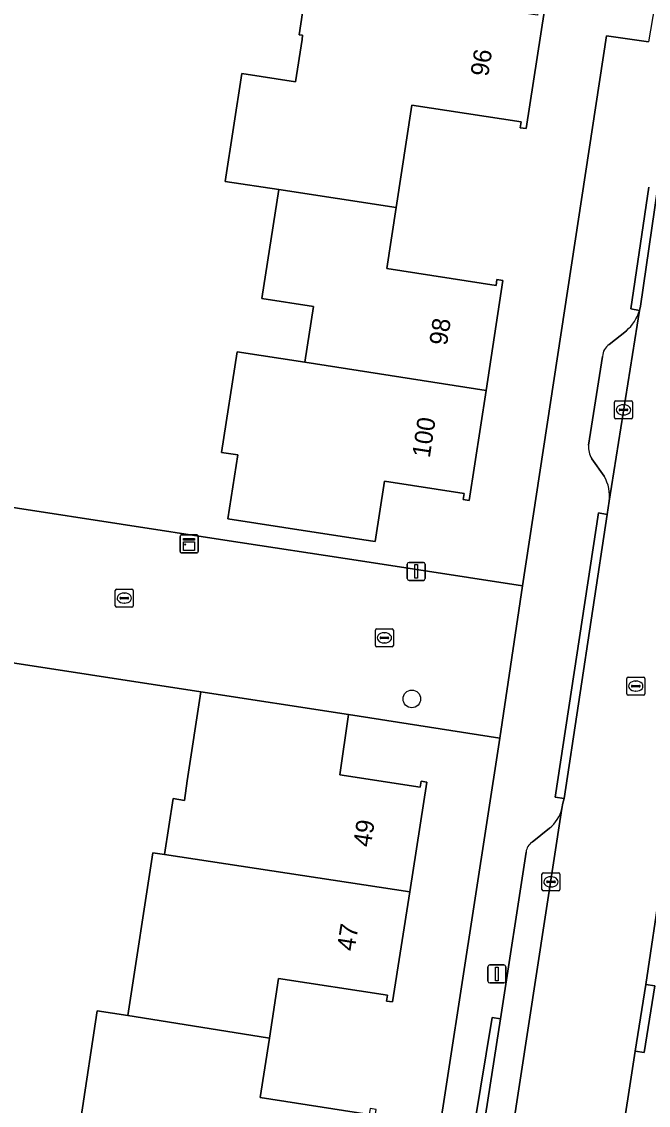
# Model space of a CAD drawing. Extents: x 161483 to 162250, y 379484 to 380833.
# Drawn here: x 161910.8 to 161945.6, y 380682.4 to 380742.6 of the extents above; entities that cross this region are included whole.
import ezdxf

# ---------------------------------------------------------------- set-up
doc = ezdxf.new("R2010")
doc.units = 0
for name, color, linetype in [('IMGEO_Boom', 7, 'Continuous'), ('IMGEO_Erf', 7, 'Continuous'), ('IMGEO_Kast', 7, 'Continuous'), ('IMGEO_Kolk', 7, 'Continuous'), ('IMGEO_Lichtmast', 7, 'Continuous'), ('IMGEO_Pand', 7, 'Continuous'), ('IMGEO_Pand_nummerreeks', 7, 'Continuous'), ('IMGEO_Parkeervlak_open', 7, 'Continuous'), ('IMGEO_Rijbaan_lokaal_open', 7, 'Continuous'), ('IMGEO_Rioolput', 7, 'Continuous'), ('IMGEO_Voetpad_open', 7, 'Continuous')]:
    doc.layers.add(name, color=color, linetype=linetype)

msp = doc.modelspace()

# ---------------------------------------------------------------- linework, layer by layer
at = {"layer": 'IMGEO_Boom'}
msp.add_circle((161932.436, 380704.97), 0.489, dxfattribs=at)
at = {"layer": 'IMGEO_Erf'}
for points in [[(161809.687, 380750), (161806.838, 380731.553), (161922.038, 380713.794), (161929.59, 380712.634), (161938.583, 380711.252), (161943.256, 380741.795), (161945.58, 380741.467)], [(161939.8, 380743.225), (161938.78, 380736.645), (161938.454, 380736.695), (161938.504, 380737.02), (161932.437, 380737.949), (161931.563, 380732.267), (161931.041, 380728.874), (161937.114, 380727.94), (161937.164, 380728.265), (161937.49, 380728.215), (161936.556, 380722.109), (161935.62, 380715.995), (161935.294, 380716.045), (161935.344, 380716.371), (161930.92, 380717.058), (161930.4, 380713.71), (161929.771, 380713.807), (161925.323, 380714.497), (161922.219, 380714.973), (161922.765, 380718.522), (161921.867, 380718.661), (161922.732, 380724.249), (161926.486, 380723.668), (161926.964, 380726.768), (161924.104, 380727.209), (161925.038, 380733.264), (161922.06, 380733.719), (161922.983, 380739.709), (161925.971, 380739.249), (161926.334, 380741.606), (161926.369, 380741.832), (161926.166, 380741.862), (161926.734, 380745.548)], [(161914.036, 380681.642), (161914.958, 380687.646), (161916.662, 380687.385), (161918.051, 380696.418), (161918.693, 380696.319), (161919.171, 380699.432), (161919.795, 380699.336), (161919.961, 380700.418), (161920.72, 380705.36), (161884.401, 380710.951), (161884.124, 380709.027), (161858.224, 380713.01), (161858.506, 380714.977), (161825.187, 380720.083)], [(161927.438, 380638.646), (161937.319, 380702.795), (161928.91, 380704.1), (161928.44, 380700.76), (161932.894, 380700.07), (161932.944, 380700.395), (161933.27, 380700.345), (161932.316, 380694.245), (161931.36, 380688.135), (161931.034, 380688.185), (161931.084, 380688.51), (161925.03, 380689.444), (161924.518, 380686.134), (161924.006, 380682.826), (161930.071, 380681.887)]]:
    msp.add_lwpolyline(points, dxfattribs=at)
at = {"layer": 'IMGEO_Kast'}
for p, q in [((161919.561, 380713.157), (161919.561, 380713.998)), ((161919.561, 380713.998), (161919.561, 380713.157)), ((161919.636, 380714.082), (161920.477, 380714.082)), ((161920.477, 380714.082), (161919.636, 380714.082)), ((161920.561, 380714.007), (161920.561, 380713.166)), ((161920.561, 380713.166), (161920.561, 380714.007)), ((161920.486, 380713.082), (161919.645, 380713.082)), ((161919.645, 380713.082), (161920.486, 380713.082))]:
    msp.add_line(p, q, dxfattribs=at)
for points in [[(161919.756, 380713.872), (161920.356, 380713.872), (161920.356, 380713.787), (161919.756, 380713.787), (161919.756, 380713.872)], [(161919.756, 380713.697), (161920.356, 380713.697), (161920.356, 380713.208), (161919.756, 380713.208), (161919.756, 380713.697)]]:
    msp.add_lwpolyline(points, dxfattribs=at)
msp.add_circle((161919.84, 380713.546), 0.0377, dxfattribs=at)
for centre, start, end in [((161919.639, 380714.004), 92.4484, 184.28452), ((161919.639, 380714.004), 92.4484, 184.28452), ((161920.483, 380714.004), 2.4484, 94.28452), ((161920.483, 380714.004), 2.4484, 94.28452), ((161919.639, 380713.16), 182.4484, 274.28452), ((161919.639, 380713.16), 182.4484, 274.28452), ((161920.483, 380713.16), 272.4484, 4.28452), ((161920.483, 380713.16), 272.4484, 4.28452)]:
    msp.add_arc(centre, 0.0779, start, end, dxfattribs=at)
at = {"layer": 'IMGEO_Kolk'}
for p, q in [((161943.691, 380720.601), (161943.691, 380721.453)), ((161943.766, 380721.527), (161944.618, 380721.527)), ((161944.179, 380721.307), (161944.204, 380721.307)), ((161944.692, 380721.453), (161944.692, 380720.601)), ((161943.95, 380721.021), (161943.95, 380721.033)), ((161944.388, 380720.984), (161943.99, 380720.984)), ((161943.993, 380721.07), (161944.391, 380721.07)), ((161944.202, 380720.747), (161944.177, 380720.747)), ((161944.434, 380721.033), (161944.434, 380721.021)), ((161944.618, 380720.527), (161943.766, 380720.527)), ((161915.959, 380710.142), (161915.959, 380710.994)), ((161916.034, 380711.068), (161916.886, 380711.068)), ((161916.96, 380710.994), (161916.96, 380710.142)), ((161916.218, 380710.562), (161916.218, 380710.574)), ((161916.656, 380710.525), (161916.258, 380710.525)), ((161916.261, 380710.611), (161916.659, 380710.611)), ((161916.447, 380710.848), (161916.472, 380710.848)), ((161916.702, 380710.574), (161916.702, 380710.562)), ((161916.886, 380710.068), (161916.034, 380710.068)), ((161916.47, 380710.288), (161916.445, 380710.288)), ((161930.407, 380707.936), (161930.407, 380708.788)), ((161930.482, 380708.862), (161931.334, 380708.862)), ((161930.895, 380708.642), (161930.92, 380708.642)), ((161931.408, 380708.788), (161931.408, 380707.936)), ((161930.666, 380708.356), (161930.666, 380708.368)), ((161931.104, 380708.319), (161930.706, 380708.319)), ((161930.709, 380708.405), (161931.107, 380708.405)), ((161930.918, 380708.082), (161930.893, 380708.082)), ((161931.15, 380708.368), (161931.15, 380708.356)), ((161931.334, 380707.862), (161930.482, 380707.862)), ((161939.74, 380695.308), (161940.592, 380695.308)), ((161939.665, 380694.382), (161939.665, 380695.234)), ((161939.924, 380694.802), (161939.924, 380694.814)), ((161940.362, 380694.765), (161939.964, 380694.765)), ((161939.967, 380694.851), (161940.365, 380694.851)), ((161940.153, 380695.088), (161940.178, 380695.088)), ((161940.408, 380694.814), (161940.408, 380694.802)), ((161940.666, 380695.234), (161940.666, 380694.382)), ((161940.592, 380694.308), (161939.74, 380694.308)), ((161940.176, 380694.528), (161940.151, 380694.528))]:
    msp.add_line(p, q, dxfattribs=at)
for points in [[(161943.691, 380720.601), (161943.691, 380721.453)], [(161943.766, 380721.527), (161944.618, 380721.527)], [(161944.692, 380721.453), (161944.692, 380720.601)], [(161944.618, 380720.527), (161943.766, 380720.527)], [(161915.959, 380710.142), (161915.959, 380710.994)], [(161916.034, 380711.068), (161916.886, 380711.068)], [(161916.96, 380710.994), (161916.96, 380710.142)], [(161916.886, 380710.068), (161916.034, 380710.068)], [(161930.407, 380707.936), (161930.407, 380708.788)], [(161930.482, 380708.862), (161931.334, 380708.862)], [(161931.408, 380708.788), (161931.408, 380707.936)], [(161931.334, 380707.862), (161930.482, 380707.862)], [(161939.74, 380695.308), (161940.592, 380695.308)], [(161939.665, 380694.382), (161939.665, 380695.234)], [(161940.666, 380695.234), (161940.666, 380694.382)], [(161940.592, 380694.308), (161939.74, 380694.308)]]:
    msp.add_lwpolyline(points, dxfattribs=at)
for centre, radius, start, end in [((161943.768, 380721.451), 0.0765, 91.55205, 178.44795), ((161943.768, 380721.451), 0.0765, 91.55205, 178.44795), ((161944.616, 380721.451), 0.0765, 1.55205, 88.44795), ((161944.616, 380721.451), 0.0765, 1.55205, 88.44795), ((161943.768, 380720.603), 0.0765, 181.55205, 268.44795), ((161943.768, 380720.603), 0.0765, 181.55205, 268.44795), ((161943.99, 380721.03), 0.0403, 85.87752, 175.75265), ((161943.987, 380721.02), 0.0366, 178.93798, 274.71019), ((161944.391, 380721.027), 0.043, 264.86636, 352.45326), ((161944.395, 380721.032), 0.0386, 1.73085, 96.63898), ((161944.616, 380720.603), 0.0765, 271.55205, 358.44795), ((161944.616, 380720.603), 0.0765, 271.55205, 358.44795), ((161916.036, 380710.992), 0.0765, 91.55205, 178.44795), ((161916.036, 380710.992), 0.0765, 91.55205, 178.44795), ((161916.884, 380710.992), 0.0765, 1.55205, 88.44795), ((161916.884, 380710.992), 0.0765, 1.55205, 88.44795), ((161916.258, 380710.571), 0.0403, 85.87752, 175.75265), ((161916.255, 380710.561), 0.0366, 178.93798, 274.71019), ((161916.659, 380710.568), 0.043, 264.86636, 352.45326), ((161916.663, 380710.573), 0.0386, 1.73085, 96.63898), ((161916.036, 380710.144), 0.0765, 181.55205, 268.44795), ((161916.036, 380710.144), 0.0765, 181.55205, 268.44795), ((161916.884, 380710.144), 0.0765, 271.55205, 358.44795), ((161916.884, 380710.144), 0.0765, 271.55205, 358.44795), ((161930.484, 380708.786), 0.0765, 91.55205, 178.44795), ((161930.484, 380708.786), 0.0765, 91.55205, 178.44795), ((161931.332, 380708.786), 0.0765, 1.55205, 88.44795), ((161931.332, 380708.786), 0.0765, 1.55205, 88.44795), ((161930.484, 380707.938), 0.0765, 181.55205, 268.44795), ((161930.484, 380707.938), 0.0765, 181.55205, 268.44795), ((161930.706, 380708.365), 0.0403, 85.87752, 175.75265), ((161930.703, 380708.355), 0.0366, 178.93798, 274.71019), ((161931.107, 380708.362), 0.043, 264.86636, 352.45326), ((161931.111, 380708.367), 0.0386, 1.73085, 96.63898), ((161931.332, 380707.938), 0.0765, 271.55205, 358.44795), ((161931.332, 380707.938), 0.0765, 271.55205, 358.44795), ((161939.742, 380695.232), 0.0765, 91.55205, 178.44795), ((161939.742, 380695.232), 0.0765, 91.55205, 178.44795), ((161940.59, 380695.232), 0.0765, 1.55205, 88.44795), ((161940.59, 380695.232), 0.0765, 1.55205, 88.44795), ((161939.964, 380694.811), 0.0403, 85.87752, 175.75265), ((161939.961, 380694.801), 0.0366, 178.93798, 274.71019), ((161940.365, 380694.808), 0.043, 264.86636, 352.45326), ((161940.369, 380694.813), 0.0386, 1.73085, 96.63898), ((161939.742, 380694.384), 0.0765, 181.55205, 268.44795), ((161939.742, 380694.384), 0.0765, 181.55205, 268.44795), ((161940.59, 380694.384), 0.0765, 271.55205, 358.44795), ((161940.59, 380694.384), 0.0765, 271.55205, 358.44795)]:
    msp.add_arc(centre, radius, start, end, dxfattribs=at)
for centre, major_axis, ratio, start_param, end_param in [((161944.178, 380721.027), (-0.387, 0.002), 0.722429, 4.712389, 7.853982), ((161944.203, 380721.027), (-0.39, 0.002), 0.717154, 1.570796, 4.712389), ((161916.446, 380710.568), (-0.387, 0.002), 0.722429, 4.712389, 7.853982), ((161916.471, 380710.568), (-0.39, 0.002), 0.717154, 1.570796, 4.712389), ((161930.894, 380708.362), (-0.387, 0.002), 0.722429, 4.712389, 7.853982), ((161930.919, 380708.362), (-0.39, 0.002), 0.717154, 1.570796, 4.712389), ((161940.152, 380694.808), (-0.387, 0.002), 0.722429, 4.712389, 7.853982), ((161940.177, 380694.808), (-0.39, 0.002), 0.717154, 1.570796, 4.712389)]:
    msp.add_ellipse(centre, major_axis=major_axis, ratio=ratio, start_param=start_param, end_param=end_param, dxfattribs=at)
at = {"layer": 'IMGEO_Lichtmast'}
for p, q in [((161932.184, 380711.654), (161932.184, 380712.454)), ((161932.184, 380712.454), (161932.184, 380711.654)), ((161932.284, 380712.554), (161933.074, 380712.554)), ((161933.074, 380712.554), (161932.284, 380712.554)), ((161933.174, 380712.454), (161933.174, 380711.654)), ((161933.174, 380711.654), (161933.174, 380712.454)), ((161933.074, 380711.554), (161932.284, 380711.554)), ((161932.284, 380711.554), (161933.074, 380711.554)), ((161936.661, 380689.294), (161936.661, 380690.094)), ((161936.661, 380690.094), (161936.661, 380689.294)), ((161936.761, 380690.194), (161937.551, 380690.194)), ((161937.551, 380690.194), (161936.761, 380690.194)), ((161937.651, 380690.094), (161937.651, 380689.294)), ((161937.651, 380689.294), (161937.651, 380690.094)), ((161937.551, 380689.194), (161936.761, 380689.194)), ((161936.761, 380689.194), (161937.551, 380689.194))]:
    msp.add_line(p, q, dxfattribs=at)
for points in [[(161932.604, 380712.429), (161932.754, 380712.429), (161932.754, 380711.679), (161932.604, 380711.679), (161932.604, 380712.429)], [(161937.081, 380690.069), (161937.231, 380690.069), (161937.231, 380689.319), (161937.081, 380689.319), (161937.081, 380690.069)]]:
    msp.add_lwpolyline(points, dxfattribs=at)
for centre, start, end in [((161932.284, 380712.454), 90, 180), ((161932.284, 380712.454), 90, 180), ((161933.074, 380712.454), 0, 90), ((161933.074, 380712.454), 360, 90), ((161932.284, 380711.654), 180, 270), ((161932.284, 380711.654), 180, 270), ((161933.074, 380711.654), 270, 0), ((161933.074, 380711.654), 270, 0), ((161936.761, 380690.094), 90, 180), ((161936.761, 380690.094), 90, 180), ((161937.551, 380690.094), 0, 90), ((161937.551, 380690.094), 360, 90), ((161936.761, 380689.294), 180, 270), ((161936.761, 380689.294), 180, 270), ((161937.551, 380689.294), 270, 0), ((161937.551, 380689.294), 270, 0)]:
    msp.add_arc(centre, 0.1, start, end, dxfattribs=at)
at = {"layer": 'IMGEO_Pand'}
for points in [[(161939.8, 380743.225), (161939.474, 380743.275), (161939.424, 380742.95), (161938.654, 380743.069), (161938.822, 380744.157), (161927.832, 380745.853), (161927.761, 380745.389), (161926.734, 380745.548), (161926.166, 380741.862), (161926.369, 380741.832), (161926.334, 380741.606), (161925.971, 380739.249), (161922.983, 380739.709), (161922.06, 380733.719), (161925.038, 380733.264), (161931.563, 380732.267), (161932.437, 380737.949), (161938.504, 380737.02), (161938.454, 380736.695), (161938.78, 380736.645)], [(161931.041, 380728.874), (161931.563, 380732.267), (161925.038, 380733.264), (161924.104, 380727.209), (161926.964, 380726.768), (161926.486, 380723.668), (161936.556, 380722.109), (161937.49, 380728.215), (161937.164, 380728.265), (161937.114, 380727.94)], [(161926.486, 380723.668), (161922.732, 380724.249), (161921.867, 380718.661), (161922.765, 380718.522), (161922.219, 380714.973), (161925.323, 380714.497), (161929.771, 380713.807), (161930.4, 380713.71), (161930.92, 380717.058), (161935.344, 380716.371), (161935.294, 380716.045), (161935.62, 380715.995), (161936.556, 380722.109)], [(161932.316, 380694.245), (161933.27, 380700.345), (161932.944, 380700.395), (161932.894, 380700.07), (161928.44, 380700.76), (161928.91, 380704.1), (161920.72, 380705.36), (161919.961, 380700.418), (161919.795, 380699.336), (161919.171, 380699.432), (161918.693, 380696.319)], [(161932.316, 380694.245), (161918.693, 380696.319), (161918.051, 380696.418), (161916.662, 380687.385), (161917.93, 380687.19), (161924.518, 380686.134), (161925.03, 380689.444), (161931.084, 380688.51), (161931.034, 380688.185), (161931.36, 380688.135)], [(161924.006, 380682.826), (161924.518, 380686.134), (161917.93, 380687.19), (161916.662, 380687.385), (161914.958, 380687.646), (161914.036, 380681.642), (161913.559, 380678.534), (161916.534, 380678.075), (161919.394, 380677.633), (161929.505, 380676.071), (161930.447, 380682.162), (161930.121, 380682.212), (161930.071, 380681.887)]]:
    msp.add_lwpolyline(points, close=True, dxfattribs=at)
at = {"layer": 'IMGEO_Parkeervlak_open'}
for points in [[(161943.407, 380715.95), (161945.082, 380726.553)], [(161944.353, 380725.42), (161943.405, 380724.647)], [(161943.037, 380723.994), (161942.244, 380719.065)], [(161942.433, 380718.314), (161943.12, 380717.335)], [(161933.359, 380650.594), (161940.771, 380698.875)], [(161940.08, 380697.79), (161939.112, 380697.018)], [(161938.782, 380696.459), (161937.356, 380687.202), (161936.438, 380681.248), (161934.552, 380669.005), (161933.63, 380663.02), (161932.214, 380653.83)]]:
    msp.add_lwpolyline(points, dxfattribs=at)
for centre, radius, start, end in [((161942.835, 380727.198), 2.338, 310.49251, 343.99105), ((161943.783, 380724.004), 0.746, 120.44097, 180.75192), ((161943.685, 380719.028), 1.441, 178.53977, 209.71216), ((161941.226, 380716.22), 2.198, 352.93738, 30.47692), ((161938.865, 380699.326), 1.959, 308.33999, 346.67663), ((161939.546, 380696.385), 0.768, 124.44804, 174.44186)]:
    msp.add_arc(centre, radius, start, end, dxfattribs=at)
at = {"layer": 'IMGEO_Rijbaan_lokaal_open'}
for points in [[(161946.089, 380733.283), (161945.135, 380726.778), (161945.082, 380726.553), (161943.407, 380715.95), (161943.296, 380715.222), (161940.897, 380699.445), (161940.819, 380699.188), (161940.771, 380698.875), (161933.359, 380650.594), (161932.427, 380644.579), (161931.61, 380638.889), (161931.551, 380638.667)], [(161937.052, 380634.637), (161937.178, 380635.427), (161937.574, 380637.901), (161938.771, 380645.995), (161939.351, 380649.714), (161940.513, 380657.293), (161941.106, 380660.987), (161941.964, 380666.501), (161942.538, 380670.221), (161943.378, 380676.03), (161943.976, 380679.748), (161944.852, 380685.403), (161945.442, 380689.115), (161946.272, 380694.705), (161946.856, 380698.453), (161947.699, 380704.067)]]:
    msp.add_lwpolyline(points, dxfattribs=at)
msp.add_lwpolyline([(161922.038, 380713.794), (161806.838, 380731.553), (161805.542, 380723.095), (161813.7, 380721.85), (161821.311, 380720.678), (161821.36, 380720.995), (161825.235, 380720.397), (161825.187, 380720.083), (161858.506, 380714.977), (161858.224, 380713.01), (161884.124, 380709.027), (161884.401, 380710.951), (161920.72, 380705.36), (161928.91, 380704.1), (161937.319, 380702.795), (161938.583, 380711.252), (161929.59, 380712.634)], close=True, dxfattribs=at)
at = {"layer": 'IMGEO_Rioolput'}
for p, q in [((161944.45, 380706.18), (161945.302, 380706.18)), ((161944.375, 380705.254), (161944.375, 380706.106)), ((161944.634, 380705.674), (161944.634, 380705.686)), ((161945.072, 380705.637), (161944.674, 380705.637)), ((161944.677, 380705.723), (161945.075, 380705.723)), ((161944.863, 380705.96), (161944.888, 380705.96)), ((161945.118, 380705.686), (161945.118, 380705.674)), ((161945.376, 380706.106), (161945.376, 380705.254)), ((161945.302, 380705.18), (161944.45, 380705.18)), ((161944.886, 380705.4), (161944.861, 380705.4))]:
    msp.add_line(p, q, dxfattribs=at)
for points in [[(161944.45, 380706.18), (161945.302, 380706.18)], [(161944.375, 380705.254), (161944.375, 380706.106)], [(161945.376, 380706.106), (161945.376, 380705.254)], [(161945.302, 380705.18), (161944.45, 380705.18)]]:
    msp.add_lwpolyline(points, dxfattribs=at)
for centre, radius, start, end in [((161944.452, 380706.104), 0.0765, 91.55205, 178.44795), ((161944.452, 380706.104), 0.0765, 91.55205, 178.44795), ((161945.3, 380706.104), 0.0765, 1.55205, 88.44795), ((161945.3, 380706.104), 0.0765, 1.55205, 88.44795), ((161944.674, 380705.683), 0.0403, 85.87752, 175.75265), ((161944.671, 380705.673), 0.0366, 178.93798, 274.71019), ((161945.075, 380705.68), 0.043, 264.86636, 352.45326), ((161945.079, 380705.685), 0.0386, 1.73085, 96.63898), ((161944.452, 380705.256), 0.0765, 181.55205, 268.44795), ((161944.452, 380705.256), 0.0765, 181.55205, 268.44795), ((161945.3, 380705.256), 0.0765, 271.55205, 358.44795), ((161945.3, 380705.256), 0.0765, 271.55205, 358.44795)]:
    msp.add_arc(centre, radius, start, end, dxfattribs=at)
for centre, major_axis, ratio, start_param, end_param in [((161944.862, 380705.68), (-0.387, 0.002), 0.722429, 4.712389, 7.853982), ((161944.887, 380705.68), (-0.39, 0.002), 0.717154, 1.570796, 4.712389)]:
    msp.add_ellipse(centre, major_axis=major_axis, ratio=ratio, start_param=start_param, end_param=end_param, dxfattribs=at)
at = {"layer": 'IMGEO_Voetpad_open'}
for points in [[(162033.278, 380728.387), (162033.612, 380730.332), (162020.884, 380732.317), (162020.903, 380732.668), (162013.612, 380733.829), (162009.83, 380734.406), (162006.07, 380734.98), (161991.884, 380737.142), (161987.708, 380737.778), (161983.164, 380738.471), (161969.907, 380740.493), (161958.651, 380742.21), (161955.926, 380742.626), (161955.778, 380742.035), (161945.932, 380743.53), (161945.58, 380741.467), (161943.256, 380741.795), (161938.583, 380711.252), (161937.319, 380702.795), (161927.438, 380638.646)], [(161945.602, 380733.397), (161944.608, 380726.634), (161945.082, 380726.553), (161945.135, 380726.778), (161946.089, 380733.283)], [(161945.082, 380726.553), (161944.608, 380726.634), (161945.602, 380733.397)], [(161943.405, 380724.647), (161944.353, 380725.42)], [(161942.244, 380719.065), (161943.037, 380723.994)], [(161943.12, 380717.335), (161942.433, 380718.314)], [(161942.802, 380715.297), (161943.296, 380715.222), (161943.407, 380715.95)], [(161940.771, 380698.875), (161940.819, 380699.188), (161940.897, 380699.445), (161940.403, 380699.52), (161942.802, 380715.297)], [(161939.112, 380697.018), (161940.08, 380697.79)], [(161932.214, 380653.83), (161933.63, 380663.02), (161933.128, 380663.1), (161934.092, 380669.079), (161934.552, 380669.005), (161936.438, 380681.248), (161935.925, 380681.331), (161936.89, 380687.278), (161937.356, 380687.202), (161938.782, 380696.459)], [(161946.272, 380694.705), (161945.442, 380689.115), (161945.935, 380689.037), (161945.345, 380685.325), (161944.852, 380685.403), (161943.976, 380679.748)]]:
    msp.add_lwpolyline(points, dxfattribs=at)
for points in [[(161940.897, 380699.445), (161943.296, 380715.222), (161942.802, 380715.297), (161940.403, 380699.52)], [(161945.442, 380689.115), (161944.852, 380685.403), (161945.345, 380685.325), (161945.935, 380689.037)], [(161936.438, 380681.248), (161937.356, 380687.202), (161936.89, 380687.278), (161935.925, 380681.331)]]:
    msp.add_lwpolyline(points, close=True, dxfattribs=at)
for centre, radius, start, end in [((161942.835, 380727.198), 2.338, 310.49251, 343.99105), ((161943.783, 380724.004), 0.746, 120.44097, 180.75192), ((161943.685, 380719.028), 1.441, 178.53977, 209.71216), ((161941.226, 380716.22), 2.198, 352.93738, 30.47692), ((161938.865, 380699.326), 1.959, 308.33999, 346.67663), ((161939.546, 380696.385), 0.768, 124.44804, 174.44186)]:
    msp.add_arc(centre, radius, start, end, dxfattribs=at)

# ---------------------------------------------------------------- texts
at = {"layer": 'IMGEO_Pand_nummerreeks'}
for s, rotation, p in [('96', 81.18812, (161936.673, 380739.505)), ('98', 81.29698, (161934.382, 380724.565)), ('100', 81.29965, (161933.428, 380718.325)), ('49', 81.10932, (161930.15, 380696.703)), ('47', 81.10791, (161929.246, 380690.922))]:
    msp.add_text(s, height=1, rotation=rotation, dxfattribs=at).set_placement(p)

doc.saveas('drawing.dxf')
